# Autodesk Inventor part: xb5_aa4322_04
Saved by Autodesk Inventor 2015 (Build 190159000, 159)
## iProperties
Created: 2018-05
Part Number: xb5_aa4322_04
Checked By: TraceParts S.A.
Material: Generic
Catalog Web Link: www.traceparts.com
Document SubType Name: Modeling
Designer: TraceParts
Density: 1 g/cm^3
Appearance: Default
Company: TraceParts S.A.
Author: TraceParts
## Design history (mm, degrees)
feature "xb5_aa4322_04.ipt"
body "Solid1"
